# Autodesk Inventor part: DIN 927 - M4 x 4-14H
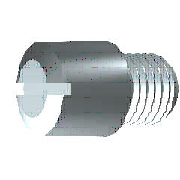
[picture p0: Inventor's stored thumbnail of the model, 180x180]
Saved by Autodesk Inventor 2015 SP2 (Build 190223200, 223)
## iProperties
Created: 2014-02
Part Number: DIN 927 - M4 x 4-14H
Material: Stahl, weich
Description: Passschraube kopflos
Document SubType Name: Modeling
Standard: DIN 927
Designer: rYan
Standards Organization: DIN
Language: de-DE
Size Designation: M4 x 4-14H
Categories: <MemberInstance><Categories><Category DisplayName="Verbindungselemente" InternalName="e4da775c-781d-43d5-af7c-5136215cf5a6" Mnemonic="FSTN"><Category DisplayNam
Density: 7.85 g/cm^3
Appearance: Halbpoliert
IsCustomPart: 0
Author: rYan
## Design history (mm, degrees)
body "Solid1"
sketch "Skizze1"
  geometry: L1 (0, 0)-(10, 0); L2 (10, 0)-(10, 2); L3 (10, 2)-(4, 2); L4 (4, 2)-(4, 2.75); L5 (4, 2.75)-(0, 2.75); L6 (0, 2.75)-(0, 0); L7 (-2, 0)-(12, 0) reference; L8 (0, -0.55)-(0, 3.3) reference; A1 r 0.6 centre (4.3, 2.52) between (4, 2) and (4.6, 2)
  constraints: 12 end point, 4 parallel, 2 collinear, 2 point on circle, 1 centre point, 1 horizontal, 1 perpendicular, 1 point on line
  dimensions: "d0" = 4 distance between parallel lines of L4 L6 (= KOH); "d1" = 6 distance between parallel lines of L2 L4 (= GEL); "d2" = 4 diameter of L3 L1 (= NND); "d3" = 5.5 diameter of L5 L1 (= KOD); "d14" = 0.6 distance of A1.end L3.end (= SBR); "d15" = 0.6 radius of A1 (= SBR)
revolve "Körper" stored, may be unused: angle "d4" = 90 deg
sketch "Skizze2"
  geometry: L1 (0, -3.85)-(0, 3.85) reference; L2 (-3.85, 0)-(3.85, 0) reference; L3 (-2.75, 0.3)-(2.75, 0.3); L4 (2.75, 0.3)-(2.75, -0.3); L5 (2.75, -0.3)-(-2.75, -0.3); L6 (-2.75, -0.3)-(-2.75, 0.3); L7 (-2.75, 0)-(2.75, 0); L8 (0, 0.3)-(0, -0.3); C1 r 2.75 at (0, 0) reference
  constraints: 12 end point, 4 midpoint, 2 collinear, 2 parallel, 1 horizontal, 1 perpendicular, 1 tangent
  dimensions: "d5" = 0.6 distance between parallel lines of L3 L5 (= SBR)
extrude "Loch" cut sketch "Skizze2" distance "d6" = 1.12 (= STI); taper "d7" = 0 deg
chamfer "Fase1" distance "d8" = 0.8 (= PHH); stored, may be unused: angle "d9" = 45 deg, second distance "d19" = 0.8 (= PHH)
feature "Gewinde" dims "d10" = 6 (= GEL), "d11" = 0
chamfer "Fase2" distance "d12" = 0.42941 (= -0.5 x GD1 + 0.5 x NND); stored, may be unused: second distance "d13" = 0.42941 (= GUL), angle "d20" = 45 deg
revolve "Nut1" stored, may be unused: angle "d16" = 90 deg
workplane "Work Plane1"
other parameters: "NND" = 4 [user parameter; used in 2 equation terms], "GEL" = 6 [user parameter; used in 3 equation terms], "KOD" = 5.5 [user parameter; used in 1 equation term], "KOH" = 4 [user parameter; used in 1 equation term], "SBR" = 0.6 [user parameter; used in 3 equation terms], "GUL" = 0.42941 (= 0.61345 x PTC) [user parameter; used in 1 equation term], "PHH" = 0.8 [user parameter; used in 2 equation terms], "GD1" = 3.14117 (= THREADDIA - 1.2269 x PTC) [user parameter; used in 1 equation term], "STI" = 1.12 [user parameter; used in 1 equation term], "d18" = 0, "d21" = 0, "d23" = 0, "THREADDIA" = 4 [user parameter; used in 1 equation term], "TOA" = 30 deg [user parameter], "NLG" = 6 (= GEL) [user parameter], "TPU" = 14.28571 (computed from PTC) [user parameter], "PTC" = 0.7 [user parameter; used in 4 equation terms], "GAL" = 0.42941 (= 0.61345 x PTC) [user parameter]
